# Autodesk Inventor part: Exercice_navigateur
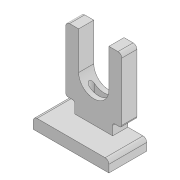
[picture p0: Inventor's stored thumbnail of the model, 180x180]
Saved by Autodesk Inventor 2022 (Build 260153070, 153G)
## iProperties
Created: 2021-03
Part Number: Exercice_navigateur
Material: Générique
Document SubType Name: Modeling
Designer: Fabian
Mass: 160.633 g
Surface Area: 306.779 cm^2
Volume: 160.633 cm^3
Density: 1 g/cm^3
Appearance: Par défaut
Author: Fabian
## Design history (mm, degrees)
sketch "Esquisse1"
  geometry: L1 (-20, 0)-(-20, 50); L2 (-20, 50)-(-37, 50); L3 (-37, 50)-(-37, -35); L4 (-37, -35)-(-25, -35); L5 (-25, -35)-(-25, -50); L6 (-25, -50)-(-50, -50); L7 (-50, -50)-(-50, -65); L8 (-50, -65)-(0, -65); L9 (0, 50)-(0, -65); L10 (-25, -50)-(0, -50); A1 r 20 centre (0, 0) between (-20, 0) and (0, -20); 2 further points
  constraints: 21 end point, 6 perpendicular, 4 point on line, 3 vertical, 2 point on circle, 1 centre point, 1 coincident, 1 horizontal, 1 midpoint, 1 tangent
  dimensions: "d0" = 40 diameter of A1; "d1" = 74 diameter of L3 L9; "d2" = 115 distance between parallel lines of L8 L2; "d3" = 30 distance between parallel lines of L8 L4; "d4" = 15 distance of L6.end L7.end; "d5" = 100 diameter of L7 L9; "d6" = 50 diameter of L5 L9; "d7" = 65 distance from line of L8 point (0, 0)
extrude "Extrusion1" new body sketch "Esquisse1" distance "d8" = 20; taper "d9" = 0 deg
sketch "Esquisse3"
  geometry: L1 (12.5, 10)-(37.5, 10); L2 (12.5, 6.5)-(37.5, 6.5); L3 (37.5, 13.5)-(12.5, 13.5); L4 (25, 0)-(25, 20) reference; A1 r 3.5 centre (12.5, 10) between (12.5, 13.5) and (12.5, 6.5); A2 r 3.5 centre (37.5, 10) between (37.5, 6.5) and (37.5, 13.5); 2 further points
  constraints: 8 end point, 4 point on circle, 4 tangent, 2 centre point, 2 midpoint, 1 coincident, 1 horizontal, 1 parallel
  dimensions: "d26" = 7 diameter of A2; "d27" = 25 distance of L1.start L1.end
extrude "Extrusion4" cut sketch "Esquisse3" extent not by distance; stored distance "d28" = 0; taper "d29" = 0 deg
extrude "Extrusion3" join sketch "Esquisse1" distance "d22" = 50; taper "d23" = 0 deg
fillet "Congé2" dims "d24" = 5, "d25" = 3
mirror "Symétrie2"
node "Solide1"
